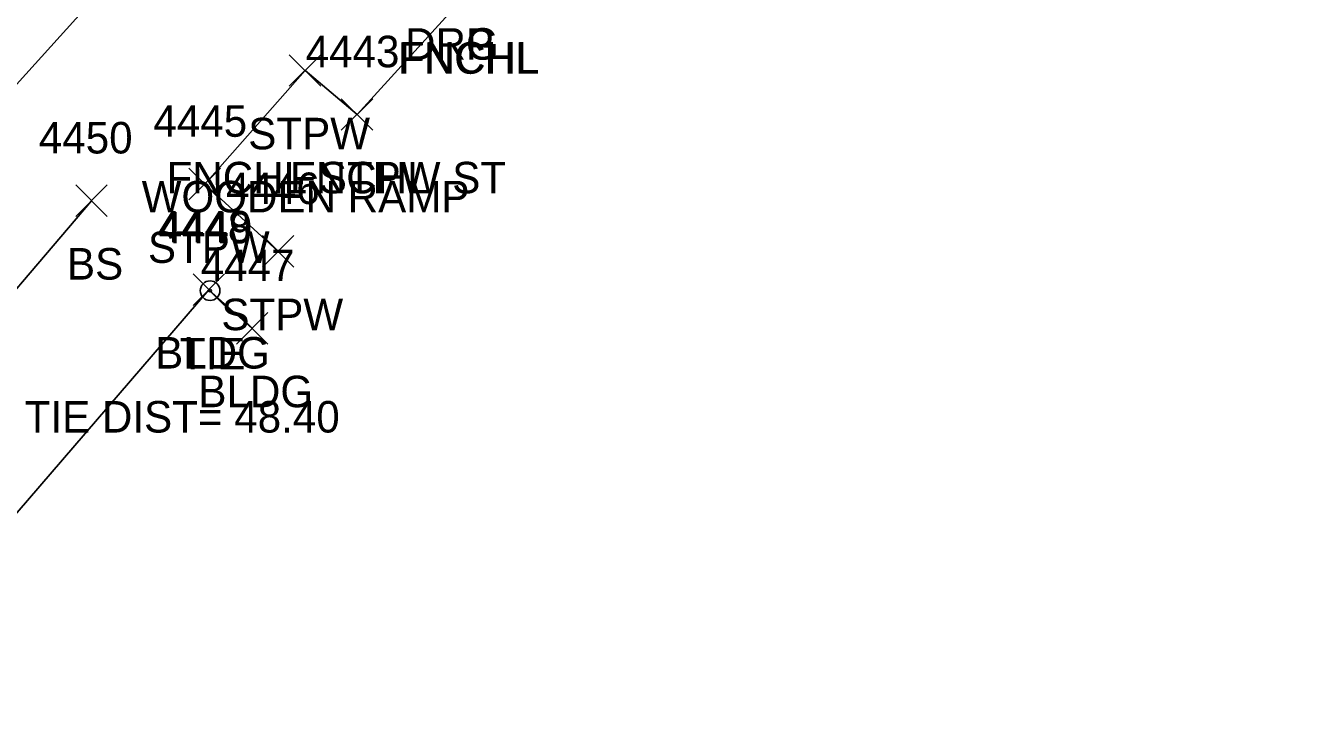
# Model space of a CAD drawing. Extents: x 1653135 to 1655489, y 602711 to 605684.
# Drawn here: x 1653286.4 to 1653367.2, y 604868.4 to 604912.5 of the extents above; entities that cross this region are included whole.
import ezdxf

# ---------------------------------------------------------------- set-up
doc = ezdxf.new("R2010")
doc.units = 0
for name, color, linetype in [('C_A', 7, 'Continuous'), ('C_C', 7, 'Continuous'), ('C_I', 7, 'Continuous'), ('CBP', 7, 'Continuous'), ('L_A', 7, 'Continuous'), ('L_C', 7, 'Continuous'), ('L_I', 7, 'Continuous'), ('L_TIC', 7, 'Continuous'), ('LBC', 7, 'Continuous'), ('LBF', 7, 'Continuous'), ('LELB', 7, 'Continuous'), ('LFNC', 7, 'Continuous'), ('PSP', 7, 'Continuous'), ('R_A', 7, 'Continuous')]:
    doc.layers.add(name, color=color, linetype=linetype)

msp = doc.modelspace()

# ---------------------------------------------------------------- linework, layer by layer
at = {"layer": 'CBP'}
for radius in [0.625, 0.0833]:
    msp.add_circle((1653298.161, 604895.644), radius, dxfattribs=at)
at = {"layer": 'L_TIC'}
for points in [[(1653303.185, 604908.609), (1653305.185, 604910.609)], [(1653305.185, 604908.609), (1653303.185, 604910.609)], [(1653303.185, 604908.609), (1653305.185, 604910.609)], [(1653305.185, 604908.609), (1653303.185, 604910.609)], [(1653306.482, 604905.816), (1653308.482, 604907.816)], [(1653308.482, 604905.816), (1653306.482, 604907.816)], [(1653306.482, 604905.816), (1653308.482, 604907.816)], [(1653308.482, 604905.816), (1653306.482, 604907.816)], [(1653306.482, 604905.816), (1653308.482, 604907.816)], [(1653308.482, 604905.816), (1653306.482, 604907.816)], [(1653306.482, 604905.816), (1653308.482, 604907.816)], [(1653308.482, 604905.816), (1653306.482, 604907.816)], [(1653296.818, 604901.407), (1653298.818, 604903.407)], [(1653298.818, 604901.407), (1653296.818, 604903.407)], [(1653296.818, 604901.407), (1653298.818, 604903.407)], [(1653298.818, 604901.407), (1653296.818, 604903.407)], [(1653289.637, 604900.347), (1653291.637, 604902.347)], [(1653291.637, 604900.347), (1653289.637, 604902.347)], [(1653289.637, 604900.347), (1653291.637, 604902.347)], [(1653291.637, 604900.347), (1653289.637, 604902.347)], [(1653301.481, 604897.138), (1653303.481, 604899.138)], [(1653303.481, 604897.138), (1653301.481, 604899.138)], [(1653301.481, 604897.138), (1653303.481, 604899.138)], [(1653303.481, 604897.138), (1653301.481, 604899.138)], [(1653297.08, 604894.703), (1653299.08, 604896.703)], [(1653299.08, 604894.703), (1653297.08, 604896.703)], [(1653297.08, 604894.703), (1653299.08, 604896.703)], [(1653299.08, 604894.703), (1653297.08, 604896.703)], [(1653299.824, 604892.249), (1653301.824, 604894.249)], [(1653301.824, 604892.249), (1653299.824, 604894.249)], [(1653299.824, 604892.249), (1653301.824, 604894.249)], [(1653301.824, 604892.249), (1653299.824, 604894.249)]]:
    msp.add_lwpolyline(points, dxfattribs=at)
at = {"layer": 'LBC'}
msp.add_lwpolyline([(1653300.824, 604893.249), (1653298.08, 604895.703), (1653282.37, 604877.469), (1653271.421, 604865.145), (1653274.149, 604862.635)], dxfattribs=at)
at = {"layer": 'LBF'}
msp.add_lwpolyline([(1653307.482, 604906.816), (1653304.185, 604909.609), (1653297.818, 604902.407), (1653302.481, 604898.138)], dxfattribs=at)
at = {"layer": 'LELB'}
msp.add_lwpolyline([(1653290.637, 604901.347), (1653272.385, 604879.943), (1653264.254, 604870.308), (1653245.327, 604851.34), (1653260.631, 604838.03)], dxfattribs=at)
at = {"layer": 'LFNC'}
msp.add_lwpolyline([(1653346.726, 604925.422), (1653330.472, 604932.376), (1653314.333, 604914.404), (1653314.395, 604914.419), (1653307.482, 604906.816)], dxfattribs=at)
at = {"layer": 'PSP'}
msp.add_lwpolyline([(1653577.495, 605132.222), (1653555.735, 605120.61), (1653541.776, 605115.966), (1653532.613, 605114.781), (1653532.247, 605110.88), (1653522.733, 605106.898), (1653507.697, 605103.522), (1653493.111, 605096.605), (1653471.403, 605083.027), (1653450.958, 605070.25), (1653430.837, 605057.523), (1653410.321, 605040.006), (1653392.797, 605023.713), (1653372.132, 605001.835), (1653359.179, 604987.803), (1653339.003, 604967.206), (1653322.133, 604948.589), (1653300.744, 604925.192), (1653278.521, 604900.611), (1653247.528, 604865.908), (1653229.566, 604844.432), (1653209.3, 604822.581), (1653182.433, 604791.771)], dxfattribs=at)

# ---------------------------------------------------------------- texts
at = {"layer": 'C_A'}
msp.add_text('TIE', height=2, dxfattribs=at).set_placement((1653296.24, 604890.644))
at = {"layer": 'C_C'}
msp.add_text('TIE DIST= 48.40', height=2, dxfattribs=at).set_placement((1653286.39, 604886.644))
at = {"layer": 'C_I'}
msp.add_text('4449', height=2, dxfattribs=at).set_placement((1653294.893, 604898.644))
at = {"layer": 'L_A'}
for s, p in [('FNCHL', (1653310.081, 604909.404)), ('FNCHL', (1653310.081, 604909.404)), ('FNCHL', (1653310.143, 604909.419)), ('FNCHL', (1653310.143, 604909.419)), ('STPW', (1653300.579, 604904.609)), ('STPW', (1653300.579, 604904.609)), ('FNCHL STPW ST', (1653295.396, 604901.816)), ('FNCHL STPW ST', (1653295.396, 604901.816)), ('FNCHL', (1653303.23, 604901.816)), ('FNCHL', (1653303.23, 604901.816)), ('STPW', (1653294.212, 604897.407)), ('STPW', (1653294.212, 604897.407)), ('BS', (1653289.077, 604896.347)), ('BS', (1653289.077, 604896.347)), ('STPW', (1653298.875, 604893.138)), ('STPW', (1653298.875, 604893.138)), ('BLDG', (1653294.67, 604890.703)), ('BLDG', (1653294.67, 604890.703)), ('BLDG', (1653297.414, 604888.249)), ('BLDG', (1653297.414, 604888.249))]:
    msp.add_text(s, height=2, dxfattribs=at).set_placement(p)
at = {"layer": 'L_C'}
msp.add_text('WOODEN RAMP', height=2, dxfattribs=at).set_placement((1653293.815, 604900.609))
msp.add_text('WOODEN RAMP', height=2, dxfattribs=at).set_placement((1653293.815, 604900.609))
at = {"layer": 'L_I'}
for s, p in [('4443', (1653304.222, 604909.816)), ('4443', (1653304.222, 604909.816)), ('4443', (1653304.222, 604909.816)), ('4443', (1653304.222, 604909.816)), ('4445', (1653294.559, 604905.407)), ('4445', (1653294.559, 604905.407)), ('4450', (1653287.29, 604904.347)), ('4450', (1653287.29, 604904.347)), ('4446', (1653299.166, 604901.138)), ('4446', (1653299.166, 604901.138)), ('4448', (1653294.82, 604898.703)), ('4448', (1653294.82, 604898.703)), ('4447', (1653297.564, 604896.249)), ('4447', (1653297.564, 604896.249))]:
    msp.add_text(s, height=2, dxfattribs=at).set_placement(p)
at = {"layer": 'R_A'}
for s in ['DRG', 'DRG', 'DRP', 'DRP']:
    msp.add_text(s, height=2, dxfattribs=at).set_placement((1653310.529, 604910.295))

doc.saveas('drawing.dxf')
